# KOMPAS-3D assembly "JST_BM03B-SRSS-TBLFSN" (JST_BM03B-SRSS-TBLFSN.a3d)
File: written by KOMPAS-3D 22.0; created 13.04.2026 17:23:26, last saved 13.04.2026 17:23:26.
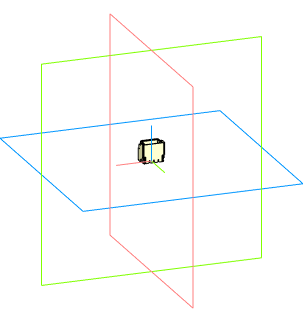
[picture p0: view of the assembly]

Document properties: Автор: Andrey; Полное имя файла: C:\Users\User1\Documents\JST_BM03B-SRSS-TBLFSN.a3d

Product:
- Component [detail]: BM03B-SRSS-TB(LF)(SN)  | qty 1  | source file: BM03B-SRSS-TB(LF)(SN).m3d
- Part/product: JST_BM03B-SRSS-TBLFSN
    Комментарий: JST_BM03B-SRSS-TBLFSN

Referenced files in C:\Users\User1\Documents\: BM03B-SRSS-TB(LF)(SN).m3d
